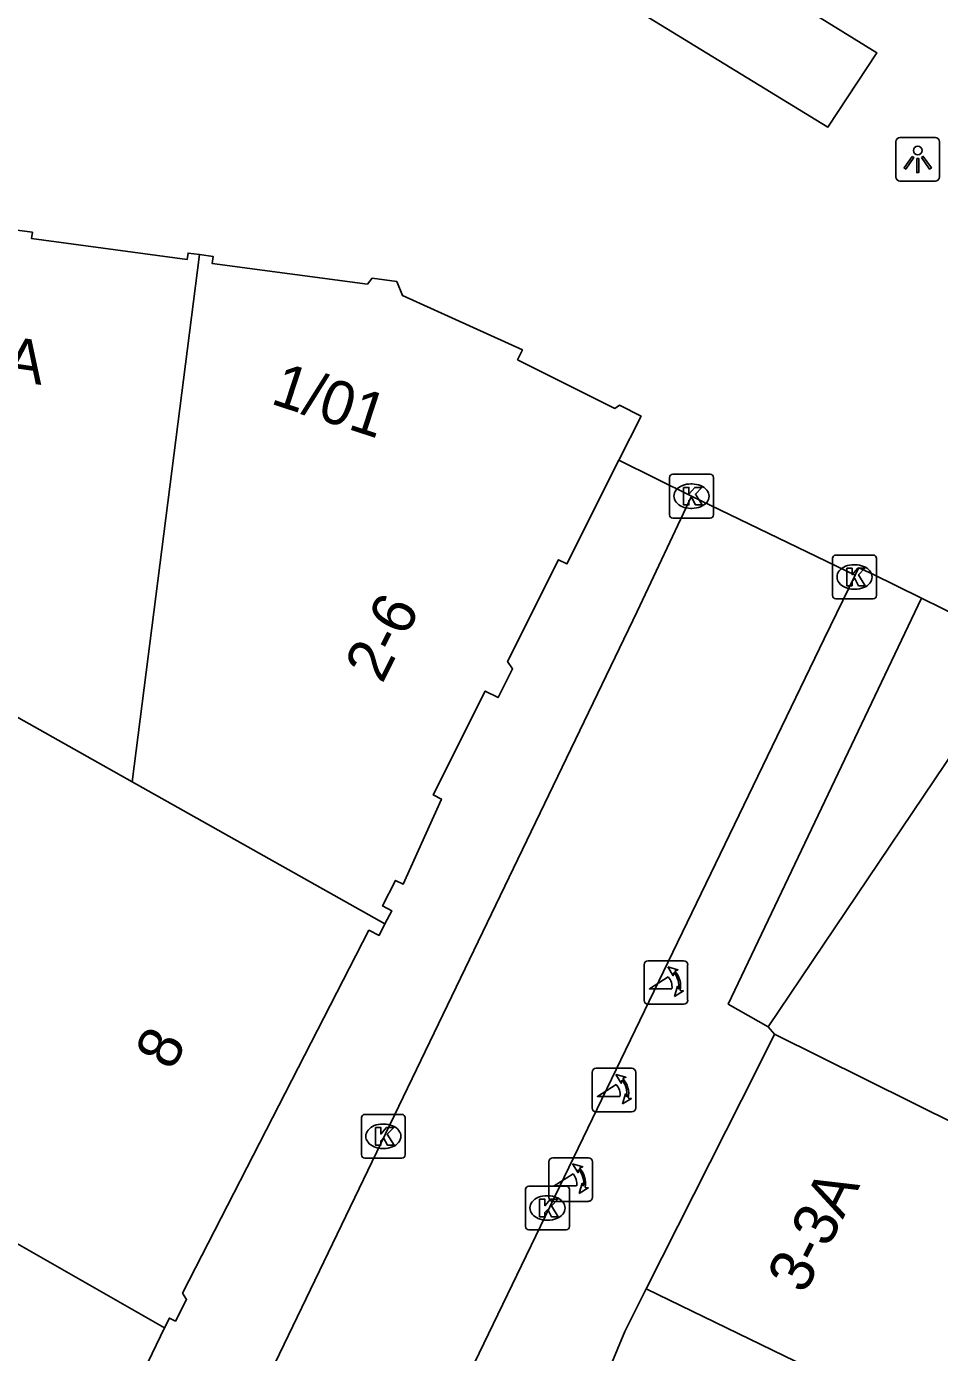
# Model space of a CAD drawing. Extents: x 160664 to 161506, y 382245 to 383288.
# Drawn here: x 161122.71 to 161143.57, y 383197.19 to 383227.49 of the extents above; entities that cross this region are included whole.
import ezdxf

# ---------------------------------------------------------------- set-up
doc = ezdxf.new("R2010")
doc.units = 0
for name, color, linetype in [('IMGEO_Fietspad_gesloten', 7, 'Continuous'), ('IMGEO_Kolk', 7, 'Continuous'), ('IMGEO_Lichtpunt', 7, 'Continuous'), ('IMGEO_Pand', 7, 'Continuous'), ('IMGEO_Pand_nummerreeks', 7, 'Continuous'), ('IMGEO_Poller', 7, 'Continuous'), ('IMGEO_Voetpad_open', 7, 'Continuous'), ('IMGEO_Woonerf_open', 7, 'Continuous')]:
    doc.layers.add(name, color=color, linetype=linetype)

msp = doc.modelspace()

# ---------------------------------------------------------------- linework, layer by layer
at = {"layer": 'IMGEO_Fietspad_gesloten'}
msp.add_lwpolyline([(161133.786, 383229.625), (161141.018, 383225.193), (161142.139, 383226.886), (161140.227, 383228.072)], dxfattribs=at)
at = {"layer": 'IMGEO_Kolk'}
for p, q in [((161137.401, 383216.333), (161137.401, 383217.185)), ((161137.476, 383217.259), (161138.328, 383217.259)), ((161138.402, 383217.185), (161138.402, 383216.333)), ((161137.889, 383217.039), (161137.914, 383217.039)), ((161137.912, 383216.479), (161137.887, 383216.479)), ((161138.328, 383216.259), (161137.476, 383216.259)), ((161141.201, 383215.413), (161142.053, 383215.413)), ((161141.126, 383214.487), (161141.126, 383215.339)), ((161141.614, 383215.193), (161141.639, 383215.193)), ((161142.127, 383215.339), (161142.127, 383214.487)), ((161141.637, 383214.633), (161141.612, 383214.633)), ((161142.053, 383214.413), (161141.201, 383214.413)), ((161130.362, 383201.706), (161130.362, 383202.558)), ((161130.437, 383202.632), (161131.289, 383202.632)), ((161130.85, 383202.412), (161130.875, 383202.412)), ((161131.363, 383202.558), (161131.363, 383201.706)), ((161130.873, 383201.852), (161130.848, 383201.852)), ((161131.289, 383201.632), (161130.437, 383201.632)), ((161134.111, 383200.068), (161134.111, 383200.92)), ((161134.186, 383200.994), (161135.038, 383200.994)), ((161135.112, 383200.92), (161135.112, 383200.068)), ((161134.599, 383200.774), (161134.624, 383200.774)), ((161134.622, 383200.214), (161134.597, 383200.214)), ((161135.038, 383199.994), (161134.186, 383199.994))]:
    msp.add_line(p, q, dxfattribs=at)
for points in [[(161137.401, 383216.333), (161137.401, 383217.185)], [(161137.476, 383217.259), (161138.328, 383217.259)], [(161138.402, 383217.185), (161138.402, 383216.333)], [(161137.722, 383216.959), (161137.845, 383216.959), (161137.845, 383216.808), (161137.975, 383216.959), (161138.139, 383216.959), (161137.993, 383216.808), (161138.146, 383216.559), (161137.994, 383216.559), (161137.909, 383216.723), (161137.845, 383216.656), (161137.845, 383216.559), (161137.722, 383216.559), (161137.722, 383216.959)], [(161138.328, 383216.259), (161137.476, 383216.259)], [(161141.201, 383215.413), (161142.053, 383215.413)], [(161141.126, 383214.487), (161141.126, 383215.339)], [(161141.447, 383215.113), (161141.57, 383215.113), (161141.57, 383214.962), (161141.7, 383215.113), (161141.864, 383215.113), (161141.718, 383214.962), (161141.871, 383214.713), (161141.719, 383214.713), (161141.634, 383214.877), (161141.57, 383214.81), (161141.57, 383214.713), (161141.447, 383214.713), (161141.447, 383215.113)], [(161142.127, 383215.339), (161142.127, 383214.487)], [(161142.053, 383214.413), (161141.201, 383214.413)], [(161130.362, 383201.706), (161130.362, 383202.558)], [(161130.437, 383202.632), (161131.289, 383202.632)], [(161130.683, 383202.332), (161130.806, 383202.332), (161130.806, 383202.181), (161130.936, 383202.332), (161131.1, 383202.332), (161130.954, 383202.181), (161131.107, 383201.932), (161130.955, 383201.932), (161130.87, 383202.096), (161130.806, 383202.029), (161130.806, 383201.932), (161130.683, 383201.932), (161130.683, 383202.332)], [(161131.363, 383202.558), (161131.363, 383201.706)], [(161131.289, 383201.632), (161130.437, 383201.632)], [(161134.111, 383200.068), (161134.111, 383200.92)], [(161134.186, 383200.994), (161135.038, 383200.994)], [(161135.112, 383200.92), (161135.112, 383200.068)], [(161134.432, 383200.694), (161134.555, 383200.694), (161134.555, 383200.543), (161134.685, 383200.694), (161134.849, 383200.694), (161134.703, 383200.543), (161134.856, 383200.294), (161134.704, 383200.294), (161134.619, 383200.458), (161134.555, 383200.391), (161134.555, 383200.294), (161134.432, 383200.294), (161134.432, 383200.694)], [(161135.038, 383199.994), (161134.186, 383199.994)]]:
    msp.add_lwpolyline(points, dxfattribs=at)
for centre, start, end in [((161137.478, 383217.183), 91.552, 178.448), ((161137.478, 383217.183), 91.552, 178.448), ((161138.326, 383217.183), 1.552, 88.448), ((161138.326, 383217.183), 1.552, 88.448), ((161137.478, 383216.335), 181.552, 268.448), ((161137.478, 383216.335), 181.552, 268.448), ((161138.326, 383216.335), 271.552, 358.448), ((161138.326, 383216.335), 271.552, 358.448), ((161141.203, 383215.337), 91.552, 178.448), ((161141.203, 383215.337), 91.552, 178.448), ((161142.051, 383215.337), 1.552, 88.448), ((161142.051, 383215.337), 1.552, 88.448), ((161141.203, 383214.489), 181.552, 268.448), ((161141.203, 383214.489), 181.552, 268.448), ((161142.051, 383214.489), 271.552, 358.448), ((161142.051, 383214.489), 271.552, 358.448), ((161130.439, 383202.556), 91.552, 178.448), ((161130.439, 383202.556), 91.552, 178.448), ((161131.287, 383202.556), 1.552, 88.448), ((161131.287, 383202.556), 1.552, 88.448), ((161130.439, 383201.708), 181.552, 268.448), ((161130.439, 383201.708), 181.552, 268.448), ((161131.287, 383201.708), 271.552, 358.448), ((161131.287, 383201.708), 271.552, 358.448), ((161134.188, 383200.918), 91.552, 178.448), ((161134.188, 383200.918), 91.552, 178.448), ((161135.036, 383200.918), 1.552, 88.448), ((161135.036, 383200.918), 1.552, 88.448), ((161134.188, 383200.07), 181.552, 268.448), ((161134.188, 383200.07), 181.552, 268.448), ((161135.036, 383200.07), 271.552, 358.448), ((161135.036, 383200.07), 271.552, 358.448)]:
    msp.add_arc(centre, 0.0765, start, end, dxfattribs=at)
for centre, major_axis, ratio, start_param, end_param in [((161137.888, 383216.759), (-0.387, 0.002), 0.722429, 4.712389, 7.853982), ((161137.913, 383216.759), (-0.39, 0.002), 0.717154, 1.570796, 4.712389), ((161141.613, 383214.913), (-0.387, 0.002), 0.722429, 4.712389, 7.853982), ((161141.638, 383214.913), (-0.39, 0.002), 0.717154, 1.570796, 4.712389), ((161130.849, 383202.132), (-0.387, 0.002), 0.722429, 4.712389, 7.853982), ((161130.874, 383202.132), (-0.39, 0.002), 0.717154, 1.570796, 4.712389), ((161134.598, 383200.494), (-0.387, 0.002), 0.722429, 4.712389, 7.853982), ((161134.623, 383200.494), (-0.39, 0.002), 0.717154, 1.570796, 4.712389)]:
    msp.add_ellipse(centre, major_axis=major_axis, ratio=ratio, start_param=start_param, end_param=end_param, dxfattribs=at)
at = {"layer": 'IMGEO_Lichtpunt'}
for p, q in [((161142.57, 383224.86), (161142.57, 383224.053)), ((161142.57, 383224.86), (161142.57, 383224.053)), ((161143.472, 383224.955), (161142.664, 383224.955)), ((161143.472, 383224.955), (161142.664, 383224.955)), ((161143.566, 383224.053), (161143.566, 383224.86)), ((161143.566, 383224.053), (161143.566, 383224.86)), ((161142.664, 383223.959), (161143.472, 383223.959)), ((161142.664, 383223.959), (161143.472, 383223.959))]:
    msp.add_line(p, q, dxfattribs=at)
for points in [[(161142.944, 383224.524), (161142.983, 383224.496), (161142.795, 383224.234), (161142.757, 383224.261), (161142.944, 383224.524)], [(161143.046, 383224.476), (161143.093, 383224.476), (161143.093, 383224.154), (161143.046, 383224.154), (161143.046, 383224.476)], [(161143.156, 383224.496), (161143.194, 383224.523), (161143.381, 383224.261), (161143.342, 383224.233), (161143.156, 383224.496)]]:
    msp.add_lwpolyline(points, dxfattribs=at)
msp.add_circle((161143.069, 383224.658), 0.0994, dxfattribs=at)
for centre, start, end in [((161142.664, 383224.86), 90, 180), ((161142.664, 383224.86), 90, 180), ((161143.472, 383224.86), 0, 90), ((161143.472, 383224.86), 0, 90), ((161142.664, 383224.053), 180, 270), ((161142.664, 383224.053), 180, 270), ((161143.472, 383224.053), 270, 0), ((161143.472, 383224.053), 270, 360)]:
    msp.add_arc(centre, 0.0946, start, end, dxfattribs=at)
at = {"layer": 'IMGEO_Pand'}
for points in [[(161126.666, 383222.278), (161126.402, 383222.314), (161126.383, 383222.168), (161122.83, 383222.646), (161122.849, 383222.788), (161122.075, 383222.892), (161122.056, 383222.755), (161118.535, 383223.229)], [(161125.128, 383210.232), (161126.666, 383222.278)], [(161126.666, 383222.278), (161126.974, 383222.237), (161126.952, 383222.078), (161130.501, 383221.601), (161130.606, 383221.737), (161131.17, 383221.661), (161131.299, 383221.347), (161134.041, 383220.101), (161133.929, 383219.876), (161136.15, 383218.763), (161136.26, 383218.836), (161136.751, 383218.589), (161136.245, 383217.58)], [(161136.245, 383217.58), (161135.056, 383215.209), (161134.865, 383215.304), (161133.701, 383212.984), (161133.815, 383212.811), (161133.486, 383212.156), (161133.192, 383212.303), (161132.003, 383209.931), (161132.188, 383209.836), (161131.314, 383207.89), (161131.144, 383207.977), (161130.845, 383207.395), (161131.056, 383207.286), (161130.901, 383206.985)], [(161116.982, 383214.814), (161125.128, 383210.232)], [(161139.653, 383204.63), (161145.479, 383213.282)], [(161130.901, 383206.985), (161125.128, 383210.232)], [(161130.901, 383206.985), (161130.765, 383206.72), (161130.535, 383206.838), (161126.277, 383198.548), (161126.37, 383198.405), (161126.114, 383197.908), (161125.976, 383197.979), (161125.868, 383197.755)], [(161125.868, 383197.755), (161110.829, 383206.349)], [(161136.869, 383198.648), (161139.406, 383203.684), (161139.801, 383204.468)], [(161139.801, 383204.468), (161139.653, 383204.63)], [(161139.801, 383204.468), (161148.222, 383200.282), (161153.886, 383196.391), (161151.659, 383193.084), (161157.001, 383189.472)], [(161135.412, 383195.339), (161136.378, 383197.673), (161136.869, 383198.648)], [(161136.869, 383198.648), (161146.04, 383194.191), (161156.392, 383188.42), (161157.001, 383189.472)], [(161125.868, 383197.755), (161122.863, 383191.511)]]:
    msp.add_lwpolyline(points, dxfattribs=at)
at = {"layer": 'IMGEO_Poller'}
for p, q in [((161136.818, 383206.049), (161136.818, 383205.242)), ((161136.818, 383206.049), (161136.818, 383205.242)), ((161137.72, 383206.144), (161136.912, 383206.144)), ((161137.72, 383206.144), (161136.912, 383206.144)), ((161137.814, 383205.242), (161137.814, 383206.049)), ((161137.814, 383205.242), (161137.814, 383206.049)), ((161136.912, 383205.147), (161137.72, 383205.147)), ((161136.912, 383205.147), (161137.72, 383205.147)), ((161135.631, 383203.591), (161135.631, 383202.784)), ((161135.631, 383203.591), (161135.631, 383202.784)), ((161136.533, 383203.686), (161135.725, 383203.686)), ((161136.533, 383203.686), (161135.725, 383203.686)), ((161136.627, 383202.784), (161136.627, 383203.591)), ((161136.627, 383202.784), (161136.627, 383203.591)), ((161135.725, 383202.689), (161136.533, 383202.689)), ((161135.725, 383202.689), (161136.533, 383202.689)), ((161134.644, 383201.547), (161134.644, 383200.74)), ((161134.644, 383201.547), (161134.644, 383200.74)), ((161135.546, 383201.642), (161134.738, 383201.642)), ((161135.546, 383201.642), (161134.738, 383201.642)), ((161135.64, 383200.74), (161135.64, 383201.547)), ((161135.64, 383200.74), (161135.64, 383201.547)), ((161134.738, 383200.645), (161135.546, 383200.645)), ((161134.738, 383200.645), (161135.546, 383200.645))]:
    msp.add_line(p, q, dxfattribs=at)
for points in [[(161137.497, 383205.873), (161137.485, 383205.8), (161137.36, 383206.005)], [(161137.36, 383206.005), (161137.591, 383205.939), (161137.52, 383205.907)], [(161137.453, 383205.5), (161136.94, 383205.5), (161137.37, 383205.775)], [(161137.513, 383205.328), (161137.579, 383205.559), (161137.609, 383205.491)], [(161137.645, 383205.464), (161137.717, 383205.453), (161137.513, 383205.328)], [(161136.31, 383203.415), (161136.298, 383203.342), (161136.173, 383203.547)], [(161136.173, 383203.547), (161136.404, 383203.481), (161136.333, 383203.449)], [(161136.266, 383203.042), (161135.753, 383203.042), (161136.183, 383203.317)], [(161136.326, 383202.87), (161136.392, 383203.101), (161136.422, 383203.033)], [(161136.458, 383203.006), (161136.53, 383202.995), (161136.326, 383202.87)], [(161135.323, 383201.371), (161135.311, 383201.298), (161135.186, 383201.503)], [(161135.186, 383201.503), (161135.417, 383201.437), (161135.346, 383201.405)], [(161135.279, 383200.998), (161134.766, 383200.998), (161135.196, 383201.273)], [(161135.339, 383200.826), (161135.405, 383201.057), (161135.435, 383200.989)], [(161135.471, 383200.962), (161135.543, 383200.951), (161135.339, 383200.826)]]:
    msp.add_lwpolyline(points, dxfattribs=at)
for centre, radius, start, end in [((161136.912, 383206.049), 0.0946, 90, 180), ((161136.912, 383206.049), 0.0946, 90, 180), ((161137.72, 383206.049), 0.0946, 0, 90), ((161137.72, 383206.049), 0.0946, 0, 90), ((161137.125, 383205.55), 0.332, 351.3247, 42.4854), ((161137.139, 383205.56), 0.476, 351.7527, 41.1691), ((161137.139, 383205.56), 0.516, 349.3569, 42.2912), ((161136.912, 383205.242), 0.0946, 180, 270), ((161136.912, 383205.242), 0.0946, 180, 270), ((161137.72, 383205.242), 0.0946, 270, 0), ((161137.72, 383205.242), 0.0946, 270, 0), ((161135.725, 383203.591), 0.0946, 90, 180), ((161135.725, 383203.591), 0.0946, 90, 180), ((161136.533, 383203.591), 0.0946, 0, 90), ((161136.533, 383203.591), 0.0946, 0, 90), ((161135.938, 383203.092), 0.332, 351.3247, 42.4854), ((161135.952, 383203.102), 0.476, 351.7527, 41.1691), ((161135.952, 383203.102), 0.516, 349.3569, 42.2912), ((161135.725, 383202.784), 0.0946, 180, 270), ((161135.725, 383202.784), 0.0946, 180, 270), ((161136.533, 383202.784), 0.0946, 270, 0), ((161136.533, 383202.784), 0.0946, 270, 0), ((161134.738, 383201.547), 0.0946, 90, 180), ((161134.738, 383201.547), 0.0946, 90, 180), ((161135.546, 383201.547), 0.0946, 0, 90), ((161135.546, 383201.547), 0.0946, 0, 90), ((161134.951, 383201.048), 0.332, 351.3247, 42.4854), ((161134.965, 383201.058), 0.476, 351.7527, 41.1691), ((161134.965, 383201.058), 0.516, 349.3569, 42.2912), ((161134.738, 383200.74), 0.0946, 180, 270), ((161134.738, 383200.74), 0.0946, 180, 270), ((161135.546, 383200.74), 0.0946, 270, 0), ((161135.546, 383200.74), 0.0946, 270, 0)]:
    msp.add_arc(centre, radius, start, end, dxfattribs=at)
at = {"layer": 'IMGEO_Voetpad_open'}
for points in [[(161137.9, 383216.761), (161136.245, 383217.58)], [(161127.08, 383194.235), (161136.662, 383214.127), (161137.9, 383216.761)]]:
    msp.add_lwpolyline(points, dxfattribs=at)
at = {"layer": 'IMGEO_Woonerf_open'}
for points in [[(161141.644, 383214.953), (161137.9, 383216.761)], [(161143.158, 383214.429), (161142.031, 383214.987), (161141.728, 383215.125), (161141.644, 383214.953)], [(161130.888, 383192.701), (161140.933, 383213.502), (161141.644, 383214.953)], [(161143.158, 383214.429), (161138.74, 383205.154), (161139.653, 383204.63)], [(161145.479, 383213.282), (161143.158, 383214.429)]]:
    msp.add_lwpolyline(points, dxfattribs=at)

# ---------------------------------------------------------------- texts
at = {"layer": 'IMGEO_Pand_nummerreeks'}
for s, rotation, p in [('1-1A', 351.8296, (161120.256, 383219.701)), ('1/01', 341.8674, (161128.26, 383218.882)), ('2-6', 63.2457, (161130.836, 383212.455)), ('8', 62.8136, (161126.04, 383203.603)), ('3-3A', 63.0688, (161140.482, 383198.5))]:
    msp.add_text(s, height=1, rotation=rotation, dxfattribs=at).set_placement(p)

doc.saveas('drawing.dxf')
